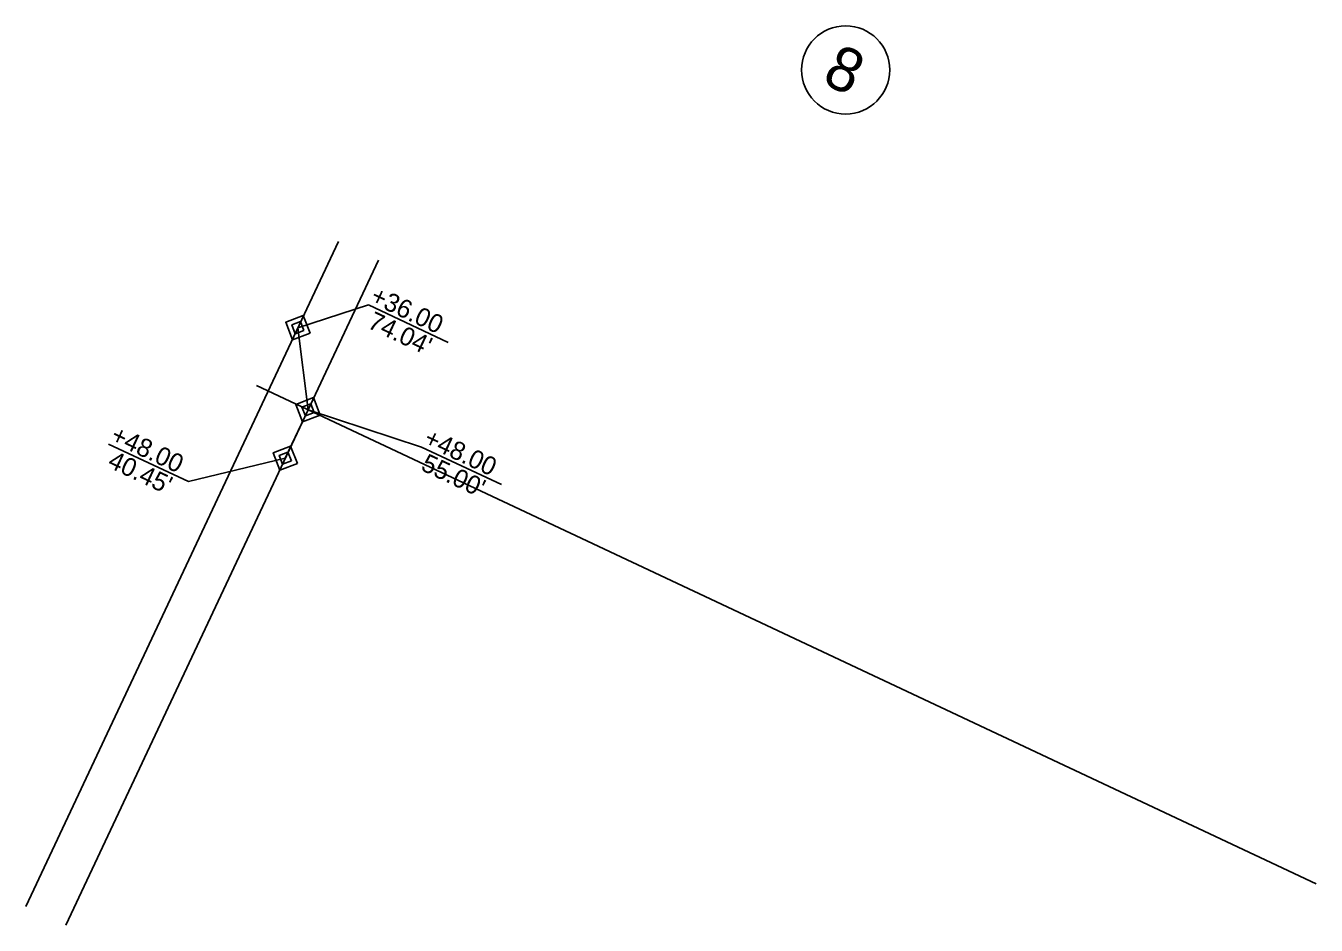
# Model space of a CAD drawing. Extents: x 1002576 to 1014655, y 551673 to 557994.
# Drawn here: x 1002575.7 to 1002926.9, y 557749.2 to 557993.9 of the extents above; entities that cross this region are included whole.
import ezdxf

# ---------------------------------------------------------------- set-up
doc = ezdxf.new("R2010")
doc.units = 0
for name, color, linetype in [('Exist Building', 7, 'Continuous'), ('Exist DTM Crownline', 7, 'Continuous'), ('Exist Hydro Stream or Body of Water', 7, 'Continuous'), ('Exist Other Culture Sign Post CELL', 7, 'Continuous'), ('Exist Structure Major Deck Tunnel Box Culvert', 7, 'Continuous'), ('Exist Utilities Power Pole CELL', 7, 'Continuous')]:
    doc.layers.add(name, color=color, linetype=linetype)

msp = doc.modelspace()

# ---------------------------------------------------------------- linework, layer by layer
at = {"layer": 'Exist Building'}
for p, q in [((1002690.68, 557907.75), (1002668.92, 557917.98)), ((1002652.5, 557889.44), (1002649.75, 557911.77)), ((1002646.31, 557876.27), (1002652.5, 557889.44)), ((1002619.96, 557869.87), (1002598.2, 557880.1)), ((1002705.19, 557869.06), (1002683.43, 557879.29))]:
    msp.add_line(p, q, dxfattribs=at)
for points in [[(1002668.92, 557917.98), (1002649.75, 557911.77)], [(1002683.43, 557879.29), (1002652.5, 557889.44)], [(1002619.96, 557869.87), (1002646.31, 557876.27)]]:
    msp.add_lwpolyline(points, dxfattribs=at)
at = {"layer": 'Exist DTM Crownline'}
for p, q in [((1002660.79, 557935.26), (1002575.69, 557754.28)), ((1002671.65, 557930.16), (1002586.55, 557749.17))]:
    msp.add_line(p, q, dxfattribs=at)
at = {"layer": 'Exist Hydro Stream or Body of Water'}
for p, q in [((1002649.75, 557911.77), (1002649.75, 557911.77)), ((1002652.5, 557889.44), (1002652.5, 557889.44)), ((1002646.31, 557876.27), (1002646.31, 557876.27))]:
    msp.add_line(p, q, dxfattribs=at)
at = {"layer": 'Exist Other Culture Sign Post CELL'}
msp.add_line((1002638.51, 557896.02), (1002926.91, 557760.4), dxfattribs=at)
at = {"layer": 'Exist Structure Major Deck Tunnel Box Culvert'}
for points in [[(1002653.04, 557910.31), (1002648.28, 557908.49), (1002646.46, 557913.24), (1002651.21, 557915.06)], [(1002651.39, 557911.04), (1002649.02, 557910.13), (1002648.1, 557912.51), (1002650.48, 557913.42)], [(1002655.79, 557887.97), (1002651.04, 557886.15), (1002649.21, 557890.9), (1002653.96, 557892.73)], [(1002654.15, 557888.7), (1002651.77, 557887.79), (1002650.86, 557890.17), (1002653.23, 557891.08)], [(1002649.6, 557874.81), (1002644.85, 557872.98), (1002643.02, 557877.73), (1002647.77, 557879.56)], [(1002647.96, 557875.54), (1002645.58, 557874.63), (1002644.67, 557877), (1002647.04, 557877.92)]]:
    msp.add_lwpolyline(points, close=True, dxfattribs=at)
at = {"layer": 'Exist Utilities Power Pole CELL'}
msp.add_line((1002798.83, 557981.92), (1002798.83, 557981.92), dxfattribs=at)
msp.add_circle((1002798.83, 557981.92), 12, dxfattribs=at)

# ---------------------------------------------------------------- texts
at = {"layer": 'Exist Building'}
for s, p in [('+36.00', (1002669.12, 557918.75)), ("74.04'", (1002668.4, 557911.84)), ('+48.00', (1002598.4, 557880.87)), ('+48.00', (1002683.63, 557880.05)), ("40.45'", (1002597.68, 557873.97)), ("55.00'", (1002682.91, 557873.15))]:
    msp.add_text(s, height=5, rotation=334.816, dxfattribs=at).set_placement(p)
at = {"layer": 'Exist Utilities Power Pole CELL'}
msp.add_text('8', height=12, rotation=334.816, dxfattribs=at).set_placement((1002791.99, 557978.51))

doc.saveas('drawing.dxf')
